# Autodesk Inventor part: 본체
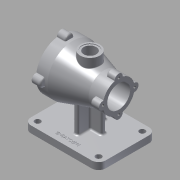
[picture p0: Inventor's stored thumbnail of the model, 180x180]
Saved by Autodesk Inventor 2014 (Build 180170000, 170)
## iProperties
Created: 2020-12
Part Number: 본체
Material: 알루미늄 6061
Document SubType Name: Modeling
Designer: kh
Density: 2.71 g/cm^3
Appearance: 알루미늄 - 평지
Mass: 1037.41 g
Surface Area: 870.977 cm^2
Volume: 382.81 cm^3
Author: kh
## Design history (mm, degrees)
sketch "스케치2"
  geometry: L1 (65, 50)-(-65, 50); L2 (-65, 50)-(-65, -50); L3 (-65, -50)-(65, -50); L4 (65, -50)-(65, 50); L5 (65, 50)-(-65, -50); L6 (-65, 50)-(65, -50); 1 further point
  constraints: 12 end point, 2 midpoint, 2 parallel, 1 horizontal, 1 perpendicular
  dimensions: "d0" = 130 distance between parallel lines of L4 L2; "d1" = 100 distance between parallel lines of L3 L1
extrude "돌출1" new body sketch "스케치2" distance "d2" = 12; taper "d3" = 0 deg
fillet "모깎기1" dims "d4" = 12
sketch "스케치3"
  geometry: L1 (-65, 38)-(-65, -38) reference; L2 (-53, -50)-(53, -50) reference; L3 (65, -38)-(65, 38) reference; L4 (53, 50)-(-53, 50) reference; C1 r 5 at (-53, 38); C2 r 5 at (-53, -38); C3 r 5 at (53, 38); C4 r 5 at (53, -38); A1 r 12 centre (-53, 38) between (-53, 50) and (-65, 38) reference; A2 r 12 centre (-53, -38) between (-65, -38) and (-53, -50) reference; A3 r 12 centre (53, -38) between (53, -50) and (65, -38) reference; A4 r 12 centre (53, 38) between (65, 38) and (53, 50) reference; 1 further point
  constraints: 4 centre point, 4 coincident
  dimensions: "d5" = 10 diameter of C1; "d6" = 10 diameter of C2; "d7" = 10 diameter of C3; "d8" = 10 diameter of C4
extrude "돌출2" cut sketch "스케치3" distance "d9" = 12; taper "d10" = 0 deg
sketch "스케치4"
  geometry: L1 (0, 0)-(0, 12); L2 (-53, 12)-(53, 12) reference; L3 (-53, 0)-(53, 0) reference; L4 (24, 12)-(24, 62); L5 (24, 62)-(-24, 62); L6 (-24, 62)-(-24, 12); L7 (24, 12)-(-24, 12)
  constraints: 10 end point, 3 midpoint, 3 perpendicular, 2 point on line, 1 collinear, 1 vertical
  dimensions: "d19" = 48 distance between parallel lines of L6 L4; "d20" = 50 distance between parallel lines of L2 L5
extrude "돌출3" join sketch "스케치4" stored distance "d21" = 8; taper "d22" = 0 deg
sketch "스케치5"
  geometry: L1 (38, 12)-(-38, 12) reference; L2 (-25, 12)-(-25, 62); L3 (-25, 62)-(25, 62); L4 (25, 62)-(25, 12); L5 (-25, 12)-(25, 12); 3 further points
  constraints: 8 end point, 4 perpendicular, 2 midpoint, 2 point on line, 1 coincident
  dimensions: "d23" = 50 distance between parallel lines of L4 L2; "d24" = 50 distance between parallel lines of L1 L3
extrude "돌출4" join sketch "스케치5" stored distance "d25" = 8; taper "d26" = 0 deg
sketch "스케치6"
  geometry: L1 (-53, 12)-(53, 12) reference; L2 (-53, 0)-(53, 0) reference; L3 (50, 82)-(-50, 82); L4 (-50, 82)-(-50, 109.5); L5 (-50, 109.5)-(-25, 109.5); L6 (-25, 109.5)-(30, 126); L7 (30, 126)-(50, 126); L8 (50, 126)-(50, 82); 3 further points
  constraints: 12 end point, 4 parallel, 2 midpoint, 1 perpendicular, 1 vertical alignment
  dimensions: "d27" = 88 diameter of L7 L3; "d28" = 55 diameter of L5 L3; "d29" = 20 distance of L6.end L7.end; "d30" = 25 distance of L4.end L5.end; "d32" = 82 distance of point (0, 0) point (0, 82); "d34" = 50 distance from line of point (0, 82) L8
revolve "회전1" sketch "스케치6" stored, may be unused: angle "d33" = 90 deg
node "작업 평면2"
sketch "스케치7"
  geometry: C1 r 17 at (0, 0); 1 further point
  constraints: 1 centre point, 1 coincident
  dimensions: "d37" = 34 diameter of C1
extrude "돌출5" join sketch "스케치7" stored distance "d38" = 8; taper "d39" = 0 deg
sketch "스케치8"
  geometry: C1 r 14 at (0, 0); 1 further point
  constraints: 1 centre point, 1 coincident
  dimensions: "d40" = 28 diameter of C1
extrude "돌출6" cut sketch "스케치8" distance "d41" = 1; taper "d42" = 0 deg
sketch "스케치9"
  geometry: C1 r 11 at (0, 0); 1 further point
  constraints: 1 centre point, 1 coincident
  dimensions: "d44" = 22 diameter of C1
extrude "돌출7" cut sketch "스케치9" distance "d45" = 35; taper "d46" = 0 deg
sketch "스케치12"
  geometry: C1 r 7 at (0, 27.5); C2 r 7 at (-27.5, 0); C3 r 7 at (0, -27.5); C4 r 7 at (27.5, 0); A1 r 27.5 centre (0, 0) between (0, 27.5) and (-27.5, 0) reference; 1 further point
  constraints: 4 centre point, 4 point on circle, 2 horizontal alignment, 2 vertical alignment
  dimensions: "d53" = 14 diameter of C1; "d54" = 14 diameter of C2; "d55" = 14 diameter of C3; "d56" = 14 diameter of C4
extrude "돌출9" join sketch "스케치12" distance "d57" = 15; taper "d58" = 0 deg
sketch "스케치14"
  geometry: C1 r 7.5 at (44, 0); C2 r 7.5 at (0, 44); C3 r 7.5 at (-44, 0); C4 r 7.5 at (0, -44); A1 r 44 centre (0, 0) between (44, 0) and (0, 44) reference; 1 further point
  constraints: 4 centre point, 4 point on circle, 2 horizontal alignment
  dimensions: "d59" = 15 diameter of C1; "d60" = 15 diameter of C2; "d61" = 15 diameter of C3; "d62" = 15 diameter of C4
extrude "돌출10" join sketch "스케치14" distance "d63" = 15; taper "d64" = 0 deg
sketch "스케치15"
  geometry: L1 (-53, 0)-(53, 0) reference; L2 (50, 82)-(-50, 82); L3 (-50, 82)-(-50, 102); L4 (-50, 102)-(-20, 102); L5 (-20, 102)-(-20, 108); L6 (-20, 108)-(27, 108); L7 (27, 108)-(27, 114); L8 (27, 114)-(50, 114); L9 (50, 114)-(50, 82); 3 further points
  constraints: 16 end point, 7 parallel, 2 midpoint, 1 perpendicular, 1 vertical alignment
  dimensions: "d65" = 82 distance of point (0, 0) point (0, 82); "d66" = 64 diameter of L8 L2; "d67" = 23 distance between parallel lines of L7 L9; "d68" = 52 diameter of L6 L2; "d69" = 47 distance between parallel lines of L7 L5; "d70" = 30 distance between parallel lines of L5 L3; "d131" = 40 diameter of L4 L2
revolve "회전2" sketch "스케치15" stored, may be unused: angle "d72" = 90 deg
hole "구멍1" diameter "d75" = 4.134; stored, may be unused: countersink angle "d79" = 90 deg, drill point angle "d81" = 118 deg; dims "d73" = 10, "d74" = 10, "d76" = 9, "d77" = 4, "d78" = 2, "d80" = 11
hole "구멍2" diameter "d84" = 4.134; stored, may be unused: countersink angle "d88" = 90 deg, drill point angle "d90" = 118 deg; dims "d82" = 10, "d83" = 10, "d85" = 9, "d86" = 4, "d87" = 2, "d89" = 11
hole "구멍3" diameter "d93" = 4.134; stored, may be unused: countersink angle "d97" = 90 deg, drill point angle "d99" = 118 deg; dims "d91" = 10, "d92" = 10, "d94" = 9, "d95" = 4, "d96" = 2, "d98" = 11
hole "구멍4" diameter "d102" = 4.134; stored, may be unused: countersink angle "d106" = 90 deg, drill point angle "d108" = 118 deg; dims "d100" = 10, "d101" = 10, "d103" = 9, "d104" = 4, "d105" = 2, "d107" = 11
sketch "스케치16"
  geometry: C1 r 32 at (-44, 0) reference; A1 r 44 centre (-44, 0) between (-36.527, -43.361) and (-0.639, -7.473) reference; A2 r 7.5 centre (0, 0) between (-0.639, -7.473) and (-0.639, 7.473) reference; A3 r 44 centre (-44, 0) between (-0.639, 7.473) and (-36.527, 43.361) reference; A4 r 7.5 centre (-44, 44) between (-36.527, 43.361) and (-51.473, 43.361) reference; A5 r 44 centre (-44, 0) between (-51.473, 43.361) and (-87.361, 7.473) reference; A6 r 7.5 centre (-88, 0) between (-87.361, 7.473) and (-87.361, -7.473) reference; A7 r 44 centre (-44, 0) between (-87.361, -7.473) and (-51.473, -43.361) reference; A8 r 7.5 centre (-44, -44) between (-51.473, -43.361) and (-36.527, -43.361) reference; 5 further points
  constraints: 4 coincident
hole "구멍5" sketch "스케치16" at (-44, 44), (-88, 0), (-44, -44), (0, 0) diameter "d109" = 4.134; stored, may be unused: countersink angle "d113" = 90 deg, drill point angle "d115" = 118 deg; dims "d110" = 9, "d111" = 4, "d112" = 2, "d114" = 11
sketch "스케치17"
  geometry: 2 further points
  constraints: 1 other
feature "엠보싱1" sketch "스케치17" dims "d0" = 130, "d1" = 100, "d116" = 0.5, "d117" = 0
fillet "모깎기5" dims "d121" = 1
fillet "모깎기6" dims "d122" = 3
fillet "모깎기7" dims "d123" = 3
fillet "모깎기8" dims "d124" = 3
fillet "모깎기9" dims "d125" = 3
fillet "모깎기10" dims "d126" = 1
node "솔리드1"
node "투영된 루프1"
node "투영된 루프3"
node "투영된 루프4"
node "투영된 루프5"
other parameters: "d36" = -127
